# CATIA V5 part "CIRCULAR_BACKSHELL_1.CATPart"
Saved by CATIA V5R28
Part number: CIRCULAR_BACKSHELL_1
Revision: --A
Publications: "Logical Termination.1", "BCP", "BCPRPoint_generated(BCP)", "BCPPlane_generated(BCP)", "BaCP", "Face_generated(BaCP)", "Face_generated(BaCP).1", "MasterKeywayAxis", "Axis_generated(BaCP)"
Bounding box of the stored display mesh (mm): x 0 to 66.178, y -16.899 to 16.899, z -16.95 to 16.95
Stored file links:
  C:\Users\ajc8720\Documents\BOEING_WORK\0001-2CES\004-AP242\Boeing-Generic_Harness_R3\CIRCULAR_BACKSHELL_1.CATPart
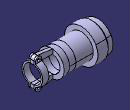
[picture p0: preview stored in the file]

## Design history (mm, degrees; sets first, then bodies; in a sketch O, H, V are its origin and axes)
Parameters
  PartNumber = "CIRCULAR_BACKSHELL_1"
AxisSystem1 "MasterKeywayAxis": origin (0, 0, 0), X (1, 0, 0), Y (0, 1, 0), Z (0, 0, 1)
Set1
  Point1: (34.417 {= Sketch2.distance(P3 V)}, 12.7, 0)
  Plane1: type 1Line1Pt, RefPoint Point1, Line Sketch2.L1
  Point2: type OnCurve, Support Sketch2.L4, Ratio 0.5
  Line1: type PtDir, RefPoint Point2, Direction (0, 1, 0), Start 0, End 5.08
  Point3: type OnCurve, Support Line1, Ratio 0.5
  Plane2: type 1Line1Pt, RefPoint Point3, Line Sketch2.L4
  Point4: type Center, Curve edge [face of Shaft1 from Sketch1.L5 | face of Shaft1 from Sketch1.L6]
  Plane3: type Tangent, Support face of Shaft1 from Sketch1.L5, RefPoint Point4
  Plane4: type OffsetPt, RefPlane Plane2, RefPoint Sketch2.P10
  Line2: type PtPt, FirstPoint vertex [face of Pad3 from Sketch5.L6 | face of Pad3 from Sketch5.L12 | end face of Pad3], SecondPoint vertex [face of Pad3 from Sketch5.L3 | face of Pad3 from Sketch5.L4 | start face of Pad3]
  Point5: type OnCurve, Support Line2, Ratio 0.5
  Plane5: type Tangent, Support face of Pad3 from Sketch5.L6, RefPoint Point5
Set2 "EGF"
  Set3 "BCP"
    Point6 "BCPRPoint": type Center, Curve edge [start face of Pad4 | face of Pad4 from Sketch6.A3]
    Plane6 "BCPPlane": type Tangent, Support start face of Pad4, RefPoint Point6
  Set4 "BaCP"
    Point7 "BaCPRPoint": type Center, Curve edge [face of Shaft1 from Sketch1.L6 | face of Shaft1 from Sketch1.L7]
    Plane7 "BaCPCPlane": type Tangent, Support face of Shaft1 from Sketch1.L7, RefPoint Point7
    Line3 "BaCPCLine": type PtDir, RefPoint Point7, Direction (0, 1, 0), Start 0, End 5.08
Body1 (main body)
  Sketch1 on xy-plane, origin (0, 0, 0), H (1, 0, 0), V (0, 1, 0)
    line L1 (0, 12.5984) -> (0, 15.3416)
    line L2 (0, 15.3416) -> (4.7625, 15.3416)
    point P3 (4.7625, 15.3416)
    line L3 (4.7625, 15.3416) -> (6.3754, 16.9545)
    line L4 (6.3754, 16.9545) -> (16.764, 16.9545)
    line L5 (16.764, 16.9545) -> (16.764, 8.8646)
    line L6 (16.764, 8.8646) -> (7.747, 8.8646)
    line L7 (7.747, 8.8646) -> (7.747, 12.5984)
    line L8 (7.747, 12.5984) -> (0, 12.5984)
    axis line L9 (-2.2417, 0) -> (20.7737, 0)
    point P9 (-2.2417, 0)
    distance P3 L1 = 4.7625
    angle L3 L4 = 45
    distance L1 L7 = 7.747
    distance L1 L5 = 16.764
    distance L6 H = 8.8646
    distance L8 H = 12.5984
    distance L2 H = 15.3416
    distance L4 H = 16.9545
    vertical: L1 V, L5 V, L7 V
    horizontal: L2 H, L4 H, L6 H, L8 H, L9 H
    coincidence: L1 V, P9 H
  Shaft1: profile Sketch1, axis Sketch1.L9, angle 360
  Sketch2 on zx-plane, origin (0, 0, 0), H (-1, 0, 0), V (0, 0, 1)
    line L1 (-34.417, 0) -> (-34.4273, 23.664)
    line L2 (-34.417, 0) -> (-36.5055, 0)
    point P3 (-34.417, 0)
    line L3 (-34.417, 0) -> (-40.767, -0.0055)
    line L4 (-40.767, -0.0055) -> (-40.6492, -135.0357)
    reference projected point E1 (-34.417, 0) from Point1
    point P7 (-40.767, -0.0055)
    line L5 (-47.117, -0.0111) -> (-46.9992, -135.0412)
    construction line L6 (-40.767, -0.0055) -> (-47.117, -0.0111)
    construction line L7 (-40.6492, -135.0357) -> (-46.9992, -135.0412)
    point P10 (-47.117, -0.0111)
    point P11 (-34.417, 0)
    angle L1 V = 0.025
    distance P3 V = 34.417
    distance L4 E1 = 6.35
    angle L3 H = 0.05
    distance L4 L5 = 6.35
    horizontal: L2 H
    coincidence: L2 P3, L1 P3, L2 H, L4 P7, L3 P7, L3 P10, L5 P10, L1 P11, L3 P11
    perpendicularity: L4 L3, L6 L4, L6 L5, L7 L4, L7 L5
  Sketch3 on Plane3, origin (16.764, 0, 0), H (0, -1, 0), V (0, 0, 1)
    circle A1 centre (0, 0) radius 8.8646
    circle A2 centre (0, 0) radius 12.2936
    radius A1 = 8.8646
    radius A2 = 12.2936
  Pad1: profile Sketch3, direction (1, 0, 0), up to Plane1
  Sketch4 on Plane2, origin (40.6326, 0, -154.0586), H (0, 1, 0), V (0.0009, 0, 1)
    circle A1 centre (0, 154.0531) radius 8.8646
    point P1 (0, 154.0531)
    circle A2 centre (0, 154.0531) radius 12.2936
    reference projected point E1 (0, 154.0531) from Sketch2.P7
    radius A1 = 8.8646
    radius A2 = 12.2936
    coincidence: P1 V, P1 E1
  Pad2: profile Sketch4, direction (-1, 0, 0.0009), up to Plane1
  Sketch5 on zx-plane, origin (0, 0, 0), H (-1, 0, 0), V (0, 0, 1)
    point P1 (0, 0)
    construction line L1 (0, 0) -> (-34.417, 0)
    point P2 (-34.417, 0)
    construction line L2 (-34.417, 0) -> (-47.117, -0.0111)
    point P3 (-47.117, -0.0111)
    point P4 (-47.0501, -76.6554)
    line L3 (-66.1776, 12.1389) -> (-66.1746, 8.7099)
    point P5 (-66.1746, 8.7099)
    line L4 (-66.1746, 8.7099) -> (-59.8246, 8.7154)
    line L5 (-47.1247, 8.8535) -> (-47.1285, 13.162)
    circle A1 centre (-63.0026, 12.1417) radius 1.8256
    arc A2 centre (-63.0026, 12.1417) radius 3.175 from (-66.1776, 12.1389) to (-62.5698, 15.287) cw
    point P7 (-66.1776, 12.1389)
    point P8 (-62.5698, 15.287)
    point P10 (-66.1594, -8.7653)
    point P12 (-66.1564, -12.1943)
    line L6 (-66.1564, -12.1943) -> (-66.1594, -8.7653)
    circle A3 centre (-62.9814, -12.1915) radius 1.8256
    line L7 (-62.5698, 15.287) -> (-47.1285, 13.162)
    point P13 (-62.5698, 15.287)
    point P14 (-47.1285, 13.162)
    point P15 (-62.543, -15.3361)
    point P16 (-66.1564, -12.1943)
    arc A4 centre (-62.9814, -12.1915) radius 3.175 from (-66.1564, -12.1943) to (-62.543, -15.3361) ccw
    point P18 (-47.1055, -13.1842)
    point P19 (-62.543, -15.3361)
    line L8 (-62.543, -15.3361) -> (-47.1055, -13.1842)
    construction line L9 (-40.7777, 12.2881) -> (-135.2639, 25.291)
    point P20 (-40.7777, 12.2881)
    line L10 (-59.8246, 8.7154) -> (-59.8247, 8.8424)
    line L11 (-59.8247, 8.8424) -> (-47.1247, 8.8535)
    point P22 (-59.8246, 8.7154)
    point P23 (-47.1247, 8.8535)
    point P24 (-59.8247, 8.8424)
    point P25 (-59.8094, -8.7598)
    point P26 (-66.1594, -8.7653)
    line L12 (-66.1594, -8.7653) -> (-59.8094, -8.7598)
    point P27 (-59.8093, -8.8868)
    point P28 (-59.8094, -8.7598)
    line L13 (-59.8094, -8.7598) -> (-59.8093, -8.8868)
    point P29 (-47.1093, -8.8757)
    point P30 (-59.8093, -8.8868)
    line L14 (-59.8093, -8.8868) -> (-47.1093, -8.8757)
    point P31 (-47.1055, -13.1842)
    point P32 (-47.1093, -8.8757)
    line L15 (-47.1093, -8.8757) -> (-47.1055, -13.1842)
    distance P1 P2 = 34.417
    angle L1 L2 = 0.05
    distance P3 P2 = 12.7
    distance L5 L3 = 19.05
    radius A1 = 1.8256
    radius A2 = 3.175
    distance L4 L2 = 8.7376
    distance A2 L2 = 15.3416
    distance P20 L2 = 12.2936
    distance P20 L5 = 6.35
    distance L10 L3 = 6.35
    distance L11 L2 = 8.8646
    horizontal: L1 H
    coincidence: P1 O, L5 P3, L7 P8, P8 A2, P4 L5, L7 L9, P10 P26, P12 P16, P15 P19, P18 P31, P25 P28, P27 P30, P29 P32
    tangency: A2 L3, A2 L7, L9 A2
    concentricity: A1 A2
    symmetry: P5 P10 L2, P7 P12 L2, L3 L6 L2, A1 A3 L2, P13 P15 L2, P7 P16 L2, A2 A4 L2, P14 P18 L2, P13 P19 L2, L7 L8 L2, P22 P25 L2, P5 P26 L2, L4 L12 L2, P24 P27 L2, P22 P28 L2, L10 L13 L2, P23 P29 L2, P24 P30 L2, L11 L14 L2, P14 P31 L2, P23 P32 L2, L5 L15 L2
    parallelism: L4 L2, L3 L5, L11 L4
    perpendicularity: L3 L2
  Pad3: profile Sketch5, direction (0, 1, 0), length 1.5875, opposite side length 1.5875
  Sketch6 on Plane5, origin (65.9234, 0, -279.1221), H (0, -1, 0), V (0.0009, 0, 1)
    arc A1 centre (0, 279.0945) radius 8.897 from (1.6764, 287.8321) to (1.6764, 270.3569) cw
    point P1 (0, 279.0945)
    point P2 (1.6764, 287.8321)
    line L1 (1.6764, 287.8321) -> (1.6764, 294.4361)
    point P3 (1.6764, 294.4361)
    line L2 (1.6764, 263.7529) -> (1.6764, 270.3569)
    point P4 (1.6764, 263.7529)
    point P5 (1.6764, 270.3569)
    line L3 (3.2639, 263.7529) -> (3.2639, 269.1311)
    point P6 (3.2639, 263.7529)
    point P7 (3.2639, 269.1311)
    arc A2 centre (0, 279.0945) radius 10.4845 from (3.2639, 269.1311) to (3.2639, 289.058) ccw
    point P8 (3.2639, 289.058)
    line L4 (3.2639, 289.058) -> (3.2639, 294.4361)
    point P9 (3.2639, 294.4361)
    line L5 (1.6764, 263.7529) -> (3.2639, 263.7529)
    line L6 (1.6764, 294.4361) -> (3.2639, 294.4361)
    construction line L7 (0, 279.0945) -> (0, 27.9514)
    point P11 (-1.6764, 287.8321)
    point P12 (-1.6764, 294.4361)
    point P13 (-1.6764, 263.7529)
    point P14 (-1.6764, 270.3569)
    point P15 (-3.2639, 263.7529)
    point P16 (-3.2639, 269.1311)
    point P17 (-3.2639, 289.058)
    point P18 (-3.2639, 294.4361)
    point P19 (0, 279.0945)
    arc A3 centre (0, 279.0945) radius 8.897 from (-1.6764, 287.8321) to (-1.6764, 270.3569) ccw
    line L8 (-1.6764, 287.8321) -> (-1.6764, 294.4361)
    line L9 (-1.6764, 263.7529) -> (-1.6764, 270.3569)
    line L10 (-3.2639, 263.7529) -> (-3.2639, 269.1311)
    arc A4 centre (0, 279.0945) radius 10.4845 from (-3.2639, 269.1311) to (-3.2639, 289.058) cw
    line L11 (-3.2639, 289.058) -> (-3.2639, 294.4361)
    line L12 (-1.6764, 263.7529) -> (-3.2639, 263.7529)
    line L13 (-1.6764, 294.4361) -> (-3.2639, 294.4361)
    reference projected point E1 (0, 279.0945) from Point5
    distance L2 L3 = 1.5875
    distance L2 P1 = 1.6764
    distance A1 A2 H = 1.5875 {= Sketch6.distance(L2 L3)}
    distance L5 P1 = 15.3416
    distance L6 P1 = 15.3416
    distance P5 P19 V = 8.7376
    vertical: L1 V, L2 V, L7 V
    coincidence: P4 L1, L2 L1, L3 L4, P19 E1
    concentricity: A2 A1
    horizontal: L5 H, L6 H
    symmetry: P2 P11 L7, P3 P12 L7, P4 P13 L7, P5 P14 L7, P6 P15 L7, P7 P16 L7, P8 P17 L7, P9 P18 L7, A1 A3 L7, L1 L8 L7, L2 L9 L7, L3 L10 L7, A2 A4 L7, L4 L11 L7, L5 L12 L7, L6 L13 L7
  Pad4: profile Sketch6, direction (-1, 0, 0.0009), length 6.35
  Fillet1: radius 3.175 {= deleted_StrainReleaseWidth /2}, on edge [start face of Pad4 | face of Pad4 from Sketch6.L13]; edge [face of Pad4 from Sketch6.L13 | end face of Pad4]; edge [start face of Pad4 | face of Pad4 from Sketch6.L6]; edge [face of Pad4 from Sketch6.L6 | end face of Pad4]; edge [start face of Pad4 | face of Pad4 from Sketch6.L12]; edge [start face of Pad4 | face of Pad4 from Sketch6.L5]; edge [face of Pad4 from Sketch6.L12 | end face of Pad4]; edge [face of Pad4 from Sketch6.L5 | end face of Pad4]
  Sketch7 on face of Pad4 from Sketch6.L11, origin (72.7908, 3.2639, -31.7287), H (1, 0, 0), V (0, 0, -1)
    point P1 (-9.7882, -43.8704)
    reference projected arc E1 centre (-9.7882, -43.8704) radius 3.175 from (-7.5431, -46.1155) to (-7.5431, -41.6253) ccw from edge [face of Pad4 from Sketch6.L11 | face of Fillet1]
    concentricity: P1 E1
  Hole1: placed by Sketch7, at (63.0026, 3.2639, 12.1417) direction (0, -1, 0), diameter 3.175, up to face of Pad4 from Sketch6.L4
  Sketch8 on face of Pad4 from Sketch6.L10, origin (57.6407, 3.2639, -47.0401), H (1, 0, 0), V (0, 0, -1)
    point P1 (5.3407, -34.8486)
    reference projected arc E1 centre (5.3407, -34.8486) radius 3.175 from (7.5858, -32.6035) to (3.0956, -32.6035) ccw from edge [face of Pad4 from Sketch6.L10 | face of Fillet1]
    concentricity: P1 E1
  Hole2: placed by Sketch8, at (62.9814, 3.2639, -12.1915) direction (0, -1, 0), diameter 3.175, up to face of Pad4 from Sketch6.L3
  Sketch9 on zx-plane, origin (0, 0, 0), H (-1, 0, 0), V (0, 0, 1)
    construction line L1 (-24.3125, 0) -> (-34.417, 0)
    point P1 (-24.3125, 0)
    point P2 (-34.417, 0)
    construction line L2 (-34.417, 0) -> (-40.767, -0.0055)
    point P3 (-40.767, -0.0055)
    construction line L3 (-40.767, -0.0055) -> (-40.7151, -59.4448)
    line L4 (-47.1285, 13.162) -> (-40.7777, 12.2881)
    point P6 (-40.7777, 12.2881)
    line L5 (-40.7777, 12.2881) -> (-40.7747, 8.8591)
    line L6 (-40.7747, 8.8591) -> (-47.1247, 8.8535)
    line L7 (-47.1247, 8.8535) -> (-47.1285, 13.162)
    axis line L8 (-40.767, -0.0055) -> (-135.4531, -0.0882)
    reference projected point E1 (-47.1285, 13.162) from edge [face of Pad3 from Sketch5.L7 | face of Pad3 from Sketch5.L5]
    distance P2 V = 34.417
    angle L1 L2 = 0.05
    distance P2 P3 = 6.35
    distance P6 L2 = 12.2936
    distance L5 L7 = 6.35
    distance L6 L2 = 8.8646
    coincidence: P1 H, L5 L3, L4 E1
    horizontal: L1 H
    perpendicularity: L3 L2
    parallelism: L8 L2
  Shaft2: profile Sketch9, axis Sketch9.L8, angle 360
Body2 "BaCP"
  Sketch10 "Sketch" on Plane7, origin (7.747, 0, 0), H (0, 1, 0), V (0, 0, 1)
    line L1 (-0.672, 0.762) -> (0.672, 0.762)
    point P1 (-0.672, 0.762)
    point P2 (0.672, 0.762)
    arc A1 centre (0, 0) radius 1.016 from (-1.016, 0) to (1.016, 0) ccw
    point P3 (0, 0)
    point P4 (-1.016, 0)
    point P5 (1.016, 0)
    reference projected point E1 (0, 0) from Point7
    arc A2 centre (0, 0) radius 1.016 from (1.016, 0) to (0.672, 0.762) ccw
    point P6 (0, 0)
    point P7 (1.016, 0)
    point P8 (0.672, 0.762)
    arc A3 centre (0, 0) radius 1.016 from (-0.672, 0.762) to (-1.016, 0) ccw
    point P9 (0, 0)
    point P10 (-0.672, 0.762)
    point P11 (-1.016, 0)
    reference projected point E2 (0, 0) from Point7
    reference projected point E3 (0, 0) from Point7
    length L1 = 1.344
    radius A1 = 1.016
    radius A3 = 1.016
    radius A2 = 1.016
    distance L1 P5 = 0.762
    distance P4 L1 = 0.762
    distance P7 L1 = 0.762
    distance P11 L1 = 0.762
    coincidence: P3 E1, P6 E2, P9 E3, P8 P2, P10 P1
    horizontal: L1 H
  Pad5: profile Sketch10, direction (1, 0, 0), length 0.508, opposite side up to Plane7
